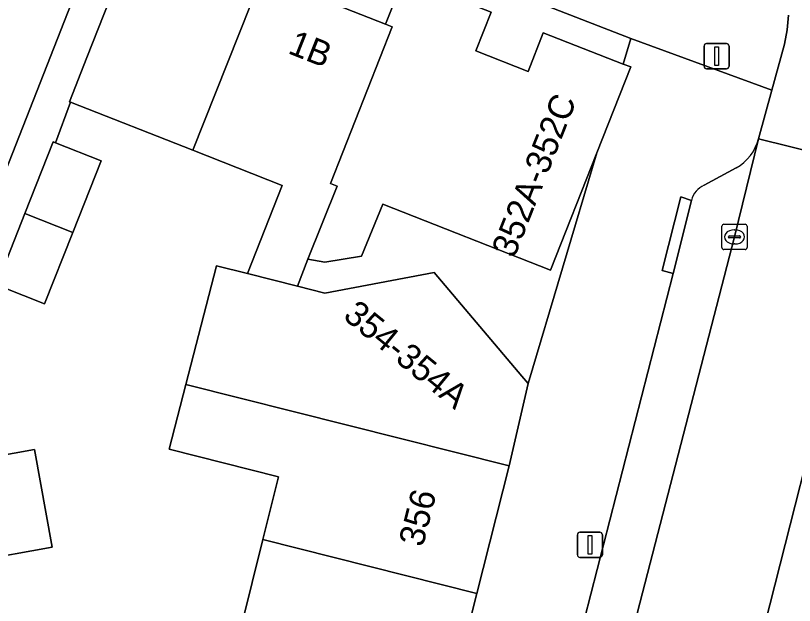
# Model space of a CAD drawing. Extents: x 161248 to 161848, y 384871 to 385383.
# Drawn here: x 161640.06 to 161670.98, y 385075.72 to 385099.14 of the extents above; entities that cross this region are included whole.
import ezdxf

# ---------------------------------------------------------------- set-up
doc = ezdxf.new("R2010")
doc.units = 0
for name, color, linetype in [('IMGEO_Erf', 7, 'Continuous'), ('IMGEO_Kolk', 7, 'Continuous'), ('IMGEO_Lichtmast', 7, 'Continuous'), ('IMGEO_Pand', 7, 'Continuous'), ('IMGEO_Pand_nummerreeks', 7, 'Continuous'), ('IMGEO_Parkeervlak_open', 7, 'Continuous'), ('IMGEO_Rijbaan_lokaal_open', 7, 'Continuous'), ('IMGEO_Voetpad_open', 7, 'Continuous')]:
    doc.layers.add(name, color=color, linetype=linetype)

msp = doc.modelspace()

# ---------------------------------------------------------------- linework, layer by layer
at = {"layer": 'IMGEO_Erf'}
for points in [[(161655.475, 385100.632), (161658.947, 385099.269), (161658.338, 385097.734), (161660.407, 385096.922), (161661.01, 385098.46), (161664.187, 385097.213), (161664.489, 385098.225), (161646.03, 385105.403), (161644.937, 385102.67), (161649.844, 385100.733), (161654.75, 385098.796)], [(161663.138, 385093.695), (161661.293, 385089.025), (161654.645, 385091.647), (161653.799, 385089.581), (161652.337, 385089.349), (161651.664, 385089.462), (161651.254, 385088.388), (161652.337, 385088.113), (161656.674, 385088.935), (161660.157, 385084.816), (161660.406, 385084.529)]]:
    msp.add_lwpolyline(points, close=True, dxfattribs=at)
for points in [[(161648.616, 385073.271), (161649.879, 385078.335), (161650.498, 385080.82), (161646.154, 385081.921), (161646.818, 385084.494), (161648.033, 385089.205), (161649.268, 385088.892), (161650.646, 385092.395), (161647.102, 385093.79), (161642.238, 385095.704), (161641.644, 385094.086), (161643.454, 385093.37), (161642.331, 385090.531), (161641.209, 385087.692), (161639.537, 385088.353)], [(161636.912, 385081.209), (161640.815, 385081.913), (161641.516, 385078.03), (161635.334, 385076.913)]]:
    msp.add_lwpolyline(points, dxfattribs=at)
at = {"layer": 'IMGEO_Kolk'}
for p, q in [((161668.176, 385090.85), (161669.028, 385090.85)), ((161668.101, 385089.924), (161668.101, 385090.776)), ((161668.589, 385090.63), (161668.614, 385090.63)), ((161669.102, 385090.776), (161669.102, 385089.924)), ((161668.36, 385090.344), (161668.36, 385090.356)), ((161668.798, 385090.307), (161668.4, 385090.307)), ((161668.403, 385090.393), (161668.801, 385090.393)), ((161668.844, 385090.356), (161668.844, 385090.344)), ((161668.612, 385090.07), (161668.587, 385090.07)), ((161669.028, 385089.85), (161668.176, 385089.85))]:
    msp.add_line(p, q, dxfattribs=at)
for points in [[(161668.176, 385090.85), (161669.028, 385090.85)], [(161668.101, 385089.924), (161668.101, 385090.776)], [(161669.102, 385090.776), (161669.102, 385089.924)], [(161669.028, 385089.85), (161668.176, 385089.85)]]:
    msp.add_lwpolyline(points, dxfattribs=at)
for centre, radius, start, end in [((161668.178, 385090.774), 0.0765, 91.552, 178.448), ((161668.178, 385090.774), 0.0765, 91.552, 178.448), ((161669.026, 385090.774), 0.0765, 1.552, 88.448), ((161669.026, 385090.774), 0.0765, 1.552, 88.448), ((161668.4, 385090.353), 0.0403, 85.8775, 175.7526), ((161668.397, 385090.343), 0.0366, 178.938, 274.7102), ((161668.801, 385090.35), 0.043, 264.8664, 352.4533), ((161668.805, 385090.355), 0.0386, 1.7309, 96.639), ((161668.178, 385089.926), 0.0765, 181.552, 268.448), ((161668.178, 385089.926), 0.0765, 181.552, 268.448), ((161669.026, 385089.926), 0.0765, 271.552, 358.448), ((161669.026, 385089.926), 0.0765, 271.552, 358.448)]:
    msp.add_arc(centre, radius, start, end, dxfattribs=at)
for centre, major_axis, ratio, start_param, end_param in [((161668.588, 385090.35), (-0.387, 0.002), 0.722429, 4.712389, 7.853982), ((161668.613, 385090.35), (-0.39, 0.002), 0.717154, 1.570796, 4.712389)]:
    msp.add_ellipse(centre, major_axis=major_axis, ratio=ratio, start_param=start_param, end_param=end_param, dxfattribs=at)
at = {"layer": 'IMGEO_Lichtmast'}
for p, q in [((161667.494, 385098.027), (161668.284, 385098.027)), ((161668.284, 385098.027), (161667.494, 385098.027)), ((161667.394, 385097.127), (161667.394, 385097.927)), ((161667.394, 385097.927), (161667.394, 385097.127)), ((161668.384, 385097.927), (161668.384, 385097.127)), ((161668.384, 385097.127), (161668.384, 385097.927)), ((161668.284, 385097.027), (161667.494, 385097.027)), ((161667.494, 385097.027), (161668.284, 385097.027)), ((161662.366, 385077.725), (161662.366, 385078.525)), ((161662.366, 385078.525), (161662.366, 385077.725)), ((161662.466, 385078.625), (161663.256, 385078.625)), ((161663.256, 385078.625), (161662.466, 385078.625)), ((161663.356, 385078.525), (161663.356, 385077.725)), ((161663.356, 385077.725), (161663.356, 385078.525)), ((161663.256, 385077.625), (161662.466, 385077.625)), ((161662.466, 385077.625), (161663.256, 385077.625))]:
    msp.add_line(p, q, dxfattribs=at)
for points in [[(161667.814, 385097.902), (161667.964, 385097.902), (161667.964, 385097.152), (161667.814, 385097.152), (161667.814, 385097.902)], [(161662.786, 385078.5), (161662.936, 385078.5), (161662.936, 385077.75), (161662.786, 385077.75), (161662.786, 385078.5)]]:
    msp.add_lwpolyline(points, dxfattribs=at)
for centre, start, end in [((161667.494, 385097.927), 90, 180), ((161667.494, 385097.927), 90, 180), ((161668.284, 385097.927), 0, 90), ((161668.284, 385097.927), 360, 90), ((161667.494, 385097.127), 180, 270), ((161667.494, 385097.127), 180, 270), ((161668.284, 385097.127), 270, 0), ((161668.284, 385097.127), 270, 0), ((161662.466, 385078.525), 90, 180), ((161662.466, 385078.525), 90, 180), ((161663.256, 385078.525), 0, 90), ((161663.256, 385078.525), 360, 90), ((161662.466, 385077.725), 180, 270), ((161662.466, 385077.725), 180, 270), ((161663.256, 385077.725), 270, 0), ((161663.256, 385077.725), 270, 0)]:
    msp.add_arc(centre, 0.1, start, end, dxfattribs=at)
at = {"layer": 'IMGEO_Pand'}
for points in [[(161643.642, 385103.129), (161637.698, 385105.451), (161634.689, 385097.731), (161633.583, 385094.893), (161639.51, 385092.589), (161640.622, 385095.425)], [(161649.844, 385100.733), (161644.937, 385102.67), (161642.887, 385097.469), (161642.197, 385095.72), (161642.238, 385095.704), (161647.102, 385093.79)], [(161654.75, 385098.796), (161649.844, 385100.733), (161647.102, 385093.79), (161650.646, 385092.395), (161649.268, 385088.892), (161651.254, 385088.388), (161651.664, 385089.462), (161652.823, 385092.366), (161652.558, 385092.47), (161655.013, 385098.692)], [(161664.187, 385097.213), (161661.01, 385098.46), (161660.407, 385096.922), (161658.338, 385097.734), (161658.947, 385099.269), (161655.475, 385100.632), (161654.75, 385098.796), (161655.013, 385098.692), (161652.558, 385092.47), (161652.823, 385092.366), (161651.664, 385089.462), (161652.337, 385089.349), (161653.799, 385089.581), (161654.645, 385091.647), (161661.293, 385089.025), (161663.138, 385093.695), (161664.483, 385097.097)], [(161641.644, 385094.086), (161641.552, 385094.122), (161640.43, 385091.283), (161642.331, 385090.531), (161643.454, 385093.37)], [(161642.331, 385090.531), (161640.43, 385091.283), (161639.307, 385088.444), (161639.537, 385088.353), (161641.209, 385087.692)], [(161656.674, 385088.935), (161652.337, 385088.113), (161651.254, 385088.388), (161649.268, 385088.892), (161648.033, 385089.205), (161646.818, 385084.494), (161659.654, 385081.261), (161660.406, 385084.529), (161660.157, 385084.816)], [(161646.154, 385081.921), (161650.498, 385080.82), (161649.879, 385078.335), (161658.369, 385076.191), (161659.654, 385081.261), (161646.818, 385084.494)], [(161636.912, 385081.209), (161636.704, 385081.171), (161634.937, 385076.841), (161635.334, 385076.913), (161641.516, 385078.03), (161640.815, 385081.913)], [(161648.616, 385073.271), (161657.09, 385071.131), (161658.369, 385076.191), (161649.879, 385078.335)]]:
    msp.add_lwpolyline(points, close=True, dxfattribs=at)
at = {"layer": 'IMGEO_Parkeervlak_open'}
for points in [[(161664.237, 385073.456), (161668.602, 385090.35), (161669.559, 385094.249)], [(161668.668, 385093.088), (161667.4, 385092.4)], [(161666.9, 385091.801), (161666.171, 385088.892), (161662.148, 385073.222)], [(161673.432, 385089.232), (161668.997, 385071.783)]]:
    msp.add_lwpolyline(points, dxfattribs=at)
for centre, radius, start, end in [((161667.712, 385094.744), 1.913, 300.0027, 344.989), ((161667.693, 385091.647), 0.808, 111.2711, 169.0238)]:
    msp.add_arc(centre, radius, start, end, dxfattribs=at)
at = {"layer": 'IMGEO_Rijbaan_lokaal_open'}
for points in [[(161670.745, 385099.15), (161670.689, 385098.575), (161670.582, 385098.007), (161670.083, 385096.175), (161669.559, 385094.249), (161674.419, 385093.044), (161675.068, 385095.448), (161675.202, 385095.915), (161675.392, 385096.41), (161675.624, 385096.886), (161675.898, 385097.34), (161676.212, 385097.767), (161676.562, 385098.164), (161676.947, 385098.529), (161677.363, 385098.858), (161677.806, 385099.148)], [(161668.997, 385071.783), (161673.432, 385089.232), (161674.419, 385093.044), (161669.559, 385094.249), (161668.602, 385090.35), (161664.237, 385073.456)]]:
    msp.add_lwpolyline(points, dxfattribs=at)
at = {"layer": 'IMGEO_Voetpad_open'}
for points in [[(161639.307, 385088.444), (161640.43, 385091.283), (161641.552, 385094.122), (161641.644, 385094.086), (161642.238, 385095.704), (161642.197, 385095.72), (161642.887, 385097.469), (161644.937, 385102.67), (161646.03, 385105.403), (161644.724, 385105.911), (161643.642, 385103.129), (161640.622, 385095.425), (161639.51, 385092.589)], [(161646.03, 385105.403), (161664.489, 385098.225), (161670.083, 385096.175), (161670.582, 385098.007), (161670.689, 385098.575), (161670.745, 385099.15)], [(161669.559, 385094.249), (161670.083, 385096.175), (161664.489, 385098.225), (161664.187, 385097.213), (161664.483, 385097.097), (161663.138, 385093.695), (161660.406, 385084.529), (161659.654, 385081.261), (161658.369, 385076.191), (161657.09, 385071.131), (161655.811, 385066.071), (161654.533, 385061.011), (161653.254, 385055.951), (161651.975, 385050.892), (161650.694, 385045.822), (161650.428, 385045.01), (161649.867, 385039.628), (161649.323, 385034.407), (161648.778, 385029.185), (161648.234, 385023.964), (161647.69, 385018.742), (161647.145, 385013.52), (161646.592, 385008.214), (161646.315, 385004.507)], [(161667.4, 385092.4), (161668.668, 385093.088)], [(161662.148, 385073.222), (161666.171, 385088.892), (161665.73, 385089.018), (161666.471, 385091.946), (161666.9, 385091.801)]]:
    msp.add_lwpolyline(points, dxfattribs=at)
msp.add_lwpolyline([(161666.9, 385091.801), (161666.471, 385091.946), (161665.73, 385089.018), (161666.171, 385088.892)], close=True, dxfattribs=at)
for centre, radius, start, end in [((161667.712, 385094.744), 1.913, 300.0027, 344.989), ((161667.693, 385091.647), 0.808, 111.2711, 169.0238)]:
    msp.add_arc(centre, radius, start, end, dxfattribs=at)

# ---------------------------------------------------------------- texts
at = {"layer": 'IMGEO_Pand_nummerreeks'}
for s, rotation, p in [('1B', 338.4568, (161650.832, 385097.655)), ('352A-352C', 68.4398, (161659.858, 385089.474)), ('354-354A', 320.718, (161653.018, 385087.137)), ('356', 75.817, (161656.228, 385078.001))]:
    msp.add_text(s, height=1, rotation=rotation, dxfattribs=at).set_placement(p)

doc.saveas('drawing.dxf')
